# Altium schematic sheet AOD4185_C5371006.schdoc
size 127 x 101 mm
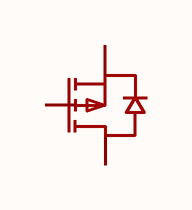
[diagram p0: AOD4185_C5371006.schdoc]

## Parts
Q?  aod4185_c5371006  [TO-252-2_L6.6-W6.1-P4.57-LS9.9-BR-CW]  (value not drawn)

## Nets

Not connected (* = marked no-connect by the designer): Q? 1(G) 2(D) 3(S)

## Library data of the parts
Q? = aod4185_c5371006: 漏源电压(Vdss):40V;连续漏极电流(Id):40A;导通电阻(RDS(on)):14mΩ@10V,30A;耗散功率(Pd):25W;阈值电压(Vgs(th)):1V;; Manufacturer: TECH PUBLIC(台舟); AddInBom: yes; ModelId: ce57f84d66384067af8a68020b6de06d; ModelName: TO-252-2L-3P_L6.6-W6.1-H2.3-LS10.1-P4.6; ModelTransform: 259.842,390.52442,0,90,0,0,-39.39,0,0; Drain to Source Voltage: 40V; Current - Continuous Drain(Id): 40A; Pd - Power Dissipation: 25W; Gate Threshold Voltage (Vgs(th)): 1V; Gate Charge(Qg): 25nC@4.5V; Input Capacitance(Ciss): 2.76nF@20V; Reverse Transfer Capacitance (Crss@Vds): 85pF@20V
